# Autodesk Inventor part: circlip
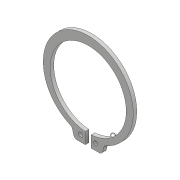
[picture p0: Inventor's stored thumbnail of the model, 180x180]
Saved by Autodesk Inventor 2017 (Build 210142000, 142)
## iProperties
Created: 2016-06
Part Number: circlip
Material: Generic
Document SubType Name: Modeling
Designer: CADCIM
Density: 1 g/cm^3
Appearance: Default
Author: CADCIM
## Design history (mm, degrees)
sketch "Sketch1"
  geometry: L1 (9.52, -25.305)-(8.665, -28.284); L2 (6.743, -29.733)-(1.75, -29.733); L3 (1.75, -29.733)-(1.75, -22.833); L4 (0, 0)-(0, -33.55); L5 (-6.743, -29.733)-(-1.75, -29.733); L6 (-1.75, -29.733)-(-1.75, -22.833); L7 (-9.52, -25.305)-(-8.665, -28.284); C1 r 1.25 at (4.55, -25.815); C2 r 1.25 at (-4.55, -25.815); A1 r 22.9 centre (0, 0) between (1.75, -22.833) and (-1.75, -22.833); A2 r 27.1 centre (0, 0.9) between (10.656, -24.017) and (-10.656, -24.017); A3 r 2 centre (-6.743, -27.733) between (-8.665, -28.284) and (-6.743, -29.733); A4 r 2 centre (-11.442, -25.856) between (-9.52, -25.305) and (-10.656, -24.017); A5 r 2 centre (11.442, -25.856) between (10.656, -24.017) and (9.52, -25.305); A6 r 2 centre (6.743, -27.733) between (6.743, -29.733) and (8.665, -28.284); 12 further points
  constraints: 18 point on circle, 14 end point, 8 centre point, 8 point on line, 8 tangent, 4 equal radius, 4 symmetric about line, 2 coincident, 2 midpoint, 1 horizontal, 1 horizontal alignment, 1 perpendicular, 1 vertical
  dimensions: "d0" = 45.8 diameter of A1; "d4" = 6.9 distance from line of L6.end L5; "d5" = 5.1 distance of point (0, 28) point (0, 22.9); "d6" = 2.5 diameter of C1; "d8" = 2 radius of A3 (derived); "d9" = 2.8 distance from line of C1.centre L3; "d10" = 3.5 distance of L5.end L2.end; "d11" = 27.1 radius of A2; "d14" = 6.5 distance of L5.end point (-8.25, -29.733); "d15" = 32 deg angle of L7 L1
extrude "Extrusion1" new body sketch "Sketch1" distance "d16" = 2.15; taper "d17" = 0 deg
body "Solid1"
other parameters: "d18" = 0
